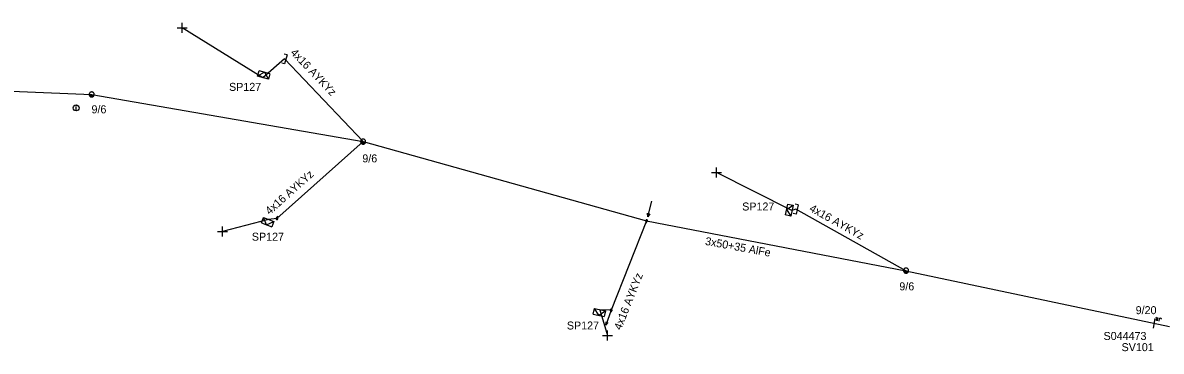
# Model space of a CAD drawing. Extents: x -717562 to -713845, y -1151196 to -1143903.
# Drawn here: x -715067 to -714924.8, y -1150294.6 to -1150253.5 of the extents above; entities that cross this region are included whole.
import ezdxf

# ---------------------------------------------------------------- set-up
doc = ezdxf.new("R2010")
doc.units = 0
for name, color, linetype in [('Vrstva 1', 7, 'Continuous'), ('Vrstva 10', 7, 'Continuous'), ('Vrstva 12', 7, 'Continuous'), ('Vrstva 13', 7, 'Continuous'), ('Vrstva 15', 7, 'Continuous'), ('Vrstva 18', 7, 'Continuous'), ('Vrstva 2', 7, 'Continuous'), ('Vrstva 29', 7, 'Continuous'), ('Vrstva 30', 7, 'Continuous'), ('Vrstva 31', 7, 'Continuous'), ('Vrstva 33', 7, 'Continuous'), ('Vrstva 34', 7, 'Continuous'), ('Vrstva 36', 7, 'Continuous'), ('Vrstva 54', 7, 'Continuous'), ('Vrstva 55', 7, 'Continuous'), ('Vrstva 59', 7, 'Continuous'), ('Vrstva 9', 7, 'Continuous')]:
    doc.layers.add(name, color=color, linetype=linetype)

# ---------------------------------------------------------------- blocks, each defined once
blk = doc.blocks.new('NN440')
at = {"layer": 'Vrstva 2'}
for points in [[(0.63, 0), (0.63, 0.06), (0.62, 0.13), (0.6, 0.19), (0.58, 0.25), (0.55, 0.31), (0.51, 0.37), (0.47, 0.42), (0.42, 0.46), (0.37, 0.51), (0.32, 0.54), (0.26, 0.57), (0.2, 0.59), (0.13, 0.61), (0.07, 0.62), (0, 0.63), (-0.06, 0.62), (-0.13, 0.61), (-0.19, 0.59), (-0.26, 0.57), (-0.31, 0.54), (-0.37, 0.51), (-0.42, 0.46), (-0.47, 0.42), (-0.51, 0.37), (-0.54, 0.31), (-0.57, 0.25), (-0.6, 0.19), (-0.62, 0.13), (-0.63, 0.06), (-0.63, 0), (-0.63, -0.07), (-0.62, -0.14), (-0.6, -0.2), (-0.57, -0.26), (-0.54, -0.32), (-0.51, -0.37), (-0.47, -0.43), (-0.42, -0.47), (-0.37, -0.51), (-0.31, -0.55), (-0.26, -0.58), (-0.19, -0.6), (-0.13, -0.62), (-0.06, -0.63), (0, -0.63), (0.07, -0.63), (0.13, -0.62), (0.2, -0.6), (0.26, -0.58), (0.32, -0.55), (0.37, -0.51), (0.42, -0.47), (0.47, -0.43), (0.51, -0.37), (0.55, -0.32), (0.58, -0.26), (0.6, -0.2), (0.62, -0.14), (0.63, -0.07), (0.63, 0)], [(-0.63, 0), (0.63, 0)], [(-0.6, -0.18), (0.57, -0.18)], [(-0.51, -0.32), (0.5, -0.32)], [(-0.37, -0.47), (0.35, -0.47)]]:
    blk.add_lwpolyline(points, dxfattribs=at)
blk = doc.blocks.new('NN560')
at = {"layer": 'Vrstva 2'}
for points in [[(2, 0), (1.59, 0.14)], [(0, 0), (2, 0)], [(2, 0), (1.59, -0.13)]]:
    blk.add_lwpolyline(points, dxfattribs=at)
blk = doc.blocks.new('NN840')
at = {"layer": 'Vrstva 15'}
for points in [[(0, 0.62), (0, -0.63)], [(-0.75, -0.71), (-0.75, -0.66)], [(-0.73, -0.76), (-0.75, -0.71)], [(-0.66, -0.8), (-0.73, -0.76)], [(-0.63, -0.8), (-0.66, -0.8)], [(-0.56, -0.76), (-0.63, -0.8)], [(-0.54, -0.71), (-0.56, -0.76)], [(-0.54, -0.38), (-0.54, -0.71)], [(-0.33, -0.38), (-0.33, -0.8)], [(-0.33, -0.64), (-0.13, -0.38)], [(-0.26, -0.56), (-0.09, -0.8)]]:
    blk.add_lwpolyline(points, dxfattribs=at)
blk = doc.blocks.new('NN565')
at = {"layer": 'Vrstva 2'}
for points in [[(0.01, 0.53), (0.01, 2.53)], [(0.16, 0.94), (0.01, 0.53), (-0.12, 0.94)]]:
    blk.add_lwpolyline(points, dxfattribs=at)
blk = doc.blocks.new('NN770')
at = {"layer": 'Vrstva 10'}
for p, q in [((0, 0.19), (0, 0.26)), ((0, -0.28), (0, 0.11))]:
    blk.add_line(p, q, dxfattribs=at)
blk.add_circle((0, -0.01), 0.375, dxfattribs=at)
blk = doc.blocks.new('NN800')
at = {"layer": 'Vrstva 1'}
for points in [[(-0.44, 0.44), (0.44, -0.44)], [(-0.44, -0.44), (0.44, 0.44)]]:
    blk.add_lwpolyline(points, dxfattribs=at)
blk = doc.blocks.new('NN630')
at = {"layer": 'Vrstva 9'}
for points in [[(0, -0.7), (-0.7, 0)], [(-0.7, -0.7), (-0.7, 0), (0.7, 0), (0.7, -0.7)], [(-0.7, -0.7), (0.7, -0.7)], [(0, -0.7), (0.7, 0)]]:
    blk.add_lwpolyline(points, dxfattribs=at)
blk = doc.blocks.new('NN500')
at = {"layer": 'Vrstva 2'}
for points in [[(0, -0.24), (0.02, -0.23), (0.05, -0.23), (0.07, -0.22), (0.09, -0.22), (0.12, -0.2), (0.14, -0.19), (0.16, -0.18), (0.17, -0.16), (0.19, -0.14), (0.2, -0.12), (0.21, -0.1), (0.22, -0.07), (0.23, -0.05), (0.23, -0.02), (0.23, 0), (0.23, 0.02), (0.23, 0.05), (0.22, 0.07), (0.21, 0.1), (0.2, 0.12), (0.19, 0.14), (0.17, 0.16), (0.16, 0.17), (0.14, 0.19), (0.12, 0.2), (0.09, 0.21), (0.07, 0.22), (0.05, 0.23), (0.02, 0.23), (0, 0.23), (-0.03, 0.23), (-0.05, 0.23), (-0.07, 0.22), (-0.1, 0.21), (-0.12, 0.2), (-0.14, 0.19), (-0.16, 0.17), (-0.18, 0.16), (-0.19, 0.14), (-0.2, 0.12), (-0.22, 0.1), (-0.22, 0.07), (-0.23, 0.05), (-0.23, 0.02), (-0.24, 0), (-0.23, -0.02), (-0.23, -0.05), (-0.22, -0.07), (-0.22, -0.1), (-0.2, -0.12), (-0.19, -0.14), (-0.18, -0.16), (-0.16, -0.18), (-0.14, -0.19), (-0.12, -0.2), (-0.1, -0.22), (-0.07, -0.22), (-0.05, -0.23), (-0.03, -0.23), (0, -0.24)], [(0, -0.24), (0.02, -0.23), (0.05, -0.23), (0.07, -0.22), (0.09, -0.22), (0.12, -0.2), (0.14, -0.19), (0.16, -0.18), (0.17, -0.16), (0.19, -0.14), (0.2, -0.12), (0.21, -0.1), (0.22, -0.07), (0.23, -0.05), (0.23, -0.02), (0.23, 0), (0.23, 0.02), (0.23, 0.05), (0.22, 0.07), (0.21, 0.1), (0.2, 0.12), (0.19, 0.14), (0.17, 0.16), (0.16, 0.17), (0.14, 0.19), (0.12, 0.2), (0.09, 0.21), (0.07, 0.22), (0.05, 0.23), (0.02, 0.23), (0, 0.23), (-0.03, 0.23), (-0.05, 0.23), (-0.07, 0.22), (-0.1, 0.21), (-0.12, 0.2), (-0.14, 0.19), (-0.16, 0.17), (-0.18, 0.16), (-0.19, 0.14), (-0.2, 0.12), (-0.22, 0.1), (-0.22, 0.07), (-0.23, 0.05), (-0.23, 0.02), (-0.24, 0), (-0.23, -0.02), (-0.23, -0.05), (-0.22, -0.07), (-0.22, -0.1), (-0.2, -0.12), (-0.19, -0.14), (-0.18, -0.16), (-0.16, -0.18), (-0.14, -0.19), (-0.12, -0.2), (-0.1, -0.22), (-0.07, -0.22), (-0.05, -0.23), (-0.03, -0.23), (0, -0.24)], [(0, -0.21), (0.02, -0.2), (0.04, -0.2), (0.06, -0.2), (0.08, -0.19), (0.1, -0.18), (0.12, -0.17), (0.14, -0.15), (0.15, -0.14), (0.16, -0.12), (0.18, -0.1), (0.19, -0.08), (0.19, -0.06), (0.2, -0.04), (0.2, -0.02), (0.2, 0), (0.2, 0.02), (0.2, 0.04), (0.19, 0.06), (0.19, 0.08), (0.18, 0.1), (0.16, 0.12), (0.15, 0.14), (0.14, 0.15), (0.12, 0.17), (0.1, 0.18), (0.08, 0.19), (0.06, 0.19), (0.04, 0.2), (0.02, 0.2), (0, 0.2), (-0.02, 0.2), (-0.04, 0.2), (-0.06, 0.19), (-0.08, 0.19), (-0.1, 0.18), (-0.12, 0.17), (-0.14, 0.15), (-0.15, 0.14), (-0.17, 0.12), (-0.18, 0.1), (-0.19, 0.08), (-0.2, 0.06), (-0.2, 0.04), (-0.21, 0.02), (-0.21, 0), (-0.21, -0.02), (-0.2, -0.04), (-0.2, -0.06), (-0.19, -0.08), (-0.18, -0.1), (-0.17, -0.12), (-0.15, -0.14), (-0.14, -0.15), (-0.12, -0.17), (-0.1, -0.18), (-0.08, -0.19), (-0.06, -0.2), (-0.04, -0.2), (-0.02, -0.2), (0, -0.21)], [(0, -0.18), (0.02, -0.18), (0.04, -0.17), (0.05, -0.17), (0.07, -0.16), (0.09, -0.15), (0.1, -0.14), (0.12, -0.13), (0.13, -0.12), (0.14, -0.1), (0.15, -0.09), (0.16, -0.07), (0.17, -0.05), (0.17, -0.04), (0.17, -0.02), (0.17, 0), (0.17, 0.02), (0.17, 0.04), (0.17, 0.05), (0.16, 0.07), (0.15, 0.09), (0.14, 0.1), (0.13, 0.12), (0.12, 0.13), (0.1, 0.14), (0.09, 0.15), (0.07, 0.16), (0.05, 0.17), (0.04, 0.17), (0.02, 0.17), (0, 0.18), (-0.02, 0.17), (-0.04, 0.17), (-0.06, 0.17), (-0.07, 0.16), (-0.09, 0.15), (-0.1, 0.14), (-0.12, 0.13), (-0.13, 0.12), (-0.14, 0.1), (-0.15, 0.09), (-0.16, 0.07), (-0.17, 0.05), (-0.17, 0.04), (-0.18, 0.02), (-0.18, 0), (-0.18, -0.02), (-0.17, -0.04), (-0.17, -0.05), (-0.16, -0.07), (-0.15, -0.09), (-0.14, -0.1), (-0.13, -0.12), (-0.12, -0.13), (-0.1, -0.14), (-0.09, -0.15), (-0.07, -0.16), (-0.06, -0.17), (-0.04, -0.17), (-0.02, -0.18), (0, -0.18)], [(0, -0.15), (0.01, -0.15), (0.03, -0.14), (0.04, -0.14), (0.06, -0.13), (0.07, -0.13), (0.08, -0.12), (0.1, -0.11), (0.11, -0.1), (0.12, -0.09), (0.13, -0.07), (0.13, -0.06), (0.14, -0.05), (0.14, -0.03), (0.14, -0.02), (0.14, 0), (0.14, 0.01), (0.14, 0.03), (0.14, 0.04), (0.13, 0.06), (0.13, 0.07), (0.12, 0.09), (0.11, 0.1), (0.1, 0.11), (0.08, 0.12), (0.07, 0.13), (0.06, 0.13), (0.04, 0.14), (0.03, 0.14), (0.01, 0.14), (0, 0.15), (-0.02, 0.14), (-0.03, 0.14), (-0.05, 0.14), (-0.06, 0.13), (-0.07, 0.13), (-0.09, 0.12), (-0.1, 0.11), (-0.11, 0.1), (-0.12, 0.09), (-0.13, 0.07), (-0.13, 0.06), (-0.14, 0.04), (-0.14, 0.03), (-0.15, 0.01), (-0.15, 0), (-0.15, -0.02), (-0.14, -0.03), (-0.14, -0.05), (-0.13, -0.06), (-0.13, -0.07), (-0.12, -0.09), (-0.11, -0.1), (-0.1, -0.11), (-0.09, -0.12), (-0.07, -0.13), (-0.06, -0.13), (-0.05, -0.14), (-0.03, -0.14), (-0.02, -0.15), (0, -0.15)], [(0, -0.12), (0.01, -0.12), (0.02, -0.11), (0.03, -0.11), (0.05, -0.11), (0.06, -0.1), (0.07, -0.09), (0.08, -0.09), (0.09, -0.08), (0.09, -0.07), (0.1, -0.06), (0.11, -0.05), (0.11, -0.04), (0.11, -0.02), (0.11, -0.01), (0.12, 0), (0.11, 0.01), (0.11, 0.02), (0.11, 0.04), (0.11, 0.05), (0.1, 0.06), (0.09, 0.07), (0.09, 0.08), (0.08, 0.09), (0.07, 0.09), (0.06, 0.1), (0.05, 0.11), (0.03, 0.11), (0.02, 0.11), (0.01, 0.12), (0, 0.12), (-0.01, 0.12), (-0.03, 0.11), (-0.04, 0.11), (-0.05, 0.11), (-0.06, 0.1), (-0.07, 0.09), (-0.08, 0.09), (-0.09, 0.08), (-0.1, 0.07), (-0.1, 0.06), (-0.11, 0.05), (-0.11, 0.04), (-0.12, 0.02), (-0.12, 0.01), (-0.12, 0), (-0.12, -0.01), (-0.12, -0.02), (-0.11, -0.04), (-0.11, -0.05), (-0.1, -0.06), (-0.1, -0.07), (-0.09, -0.08), (-0.08, -0.09), (-0.07, -0.09), (-0.06, -0.1), (-0.05, -0.11), (-0.04, -0.11), (-0.03, -0.11), (-0.01, -0.12), (0, -0.12)], [(0, -0.09), (0.01, -0.09), (0.02, -0.09), (0.03, -0.08), (0.03, -0.08), (0.04, -0.08), (0.05, -0.07), (0.06, -0.07), (0.06, -0.06), (0.07, -0.05), (0.07, -0.04), (0.08, -0.04), (0.08, -0.03), (0.08, -0.02), (0.09, -0.01), (0.09, 0), (0.09, 0.01), (0.08, 0.02), (0.08, 0.03), (0.08, 0.03), (0.07, 0.04), (0.07, 0.05), (0.06, 0.06), (0.06, 0.06), (0.05, 0.07), (0.04, 0.07), (0.03, 0.08), (0.03, 0.08), (0.02, 0.08), (0.01, 0.09), (0, 0.09), (-0.01, 0.09), (-0.02, 0.08), (-0.03, 0.08), (-0.04, 0.08), (-0.04, 0.07), (-0.05, 0.07), (-0.06, 0.06), (-0.07, 0.06), (-0.07, 0.05), (-0.08, 0.04), (-0.08, 0.03), (-0.08, 0.03), (-0.09, 0.02), (-0.09, 0.01), (-0.09, 0), (-0.09, -0.01), (-0.09, -0.02), (-0.08, -0.03), (-0.08, -0.04), (-0.08, -0.04), (-0.07, -0.05), (-0.07, -0.06), (-0.06, -0.07), (-0.05, -0.07), (-0.04, -0.08), (-0.04, -0.08), (-0.03, -0.08), (-0.02, -0.09), (-0.01, -0.09), (0, -0.09)], [(0, -0.06), (0, -0.06), (0.01, -0.06), (0.02, -0.05), (0.02, -0.05), (0.03, -0.05), (0.03, -0.05), (0.04, -0.04), (0.04, -0.04), (0.05, -0.03), (0.05, -0.03), (0.05, -0.02), (0.05, -0.02), (0.05, -0.01), (0.06, -0.01), (0.06, 0), (0.06, 0.01), (0.05, 0.01), (0.05, 0.02), (0.05, 0.02), (0.05, 0.03), (0.05, 0.03), (0.04, 0.04), (0.04, 0.04), (0.03, 0.05), (0.03, 0.05), (0.02, 0.05), (0.02, 0.05), (0.01, 0.06), (0, 0.06), (0, 0.06), (-0.01, 0.06), (-0.01, 0.06), (-0.02, 0.05), (-0.02, 0.05), (-0.03, 0.05), (-0.03, 0.05), (-0.04, 0.04), (-0.04, 0.04), (-0.05, 0.03), (-0.05, 0.03), (-0.05, 0.02), (-0.06, 0.02), (-0.06, 0.01), (-0.06, 0.01), (-0.06, 0), (-0.06, -0.01), (-0.06, -0.01), (-0.06, -0.02), (-0.05, -0.02), (-0.05, -0.03), (-0.05, -0.03), (-0.04, -0.04), (-0.04, -0.04), (-0.03, -0.05), (-0.03, -0.05), (-0.02, -0.05), (-0.02, -0.05), (-0.01, -0.06), (-0.01, -0.06), (0, -0.06)], [(0, -0.03), (0, -0.03), (0, -0.03), (0.01, -0.03), (0.01, -0.03), (0.01, -0.02), (0.02, -0.02), (0.02, -0.02), (0.02, -0.02), (0.02, -0.02), (0.02, -0.01), (0.02, -0.01), (0.03, -0.01), (0.03, -0.01), (0.03, 0), (0.03, 0), (0.03, 0), (0.03, 0.01), (0.03, 0.01), (0.02, 0.01), (0.02, 0.01), (0.02, 0.02), (0.02, 0.02), (0.02, 0.02), (0.02, 0.02), (0.01, 0.02), (0.01, 0.02), (0.01, 0.03), (0, 0.03), (0, 0.03), (0, 0.03), (0, 0.03), (-0.01, 0.03), (-0.01, 0.03), (-0.01, 0.02), (-0.02, 0.02), (-0.02, 0.02), (-0.02, 0.02), (-0.02, 0.02), (-0.02, 0.02), (-0.03, 0.01), (-0.03, 0.01), (-0.03, 0.01), (-0.03, 0.01), (-0.03, 0), (-0.03, 0), (-0.03, 0), (-0.03, -0.01), (-0.03, -0.01), (-0.03, -0.01), (-0.03, -0.01), (-0.02, -0.02), (-0.02, -0.02), (-0.02, -0.02), (-0.02, -0.02), (-0.02, -0.02), (-0.01, -0.03), (-0.01, -0.03), (-0.01, -0.03), (0, -0.03), (0, -0.03)], [(0.23, 0), (0.7, 0)]]:
    blk.add_lwpolyline(points, dxfattribs=at)
blk = doc.blocks.new('NN515')
at = {"layer": 'Vrstva 2'}
for points in [[(-0.59, 0.18), (0.59, 0.18)], [(-0.59, 0.18), (-0.59, -0.18)], [(0.59, 0.18), (0.59, -0.18)]]:
    blk.add_lwpolyline(points, dxfattribs=at)

msp = doc.modelspace()

# ---------------------------------------------------------------- linework, layer by layer
at = {"layer": 'Vrstva 1'}
msp.add_lwpolyline([(-715091.6, -1150261.12), (-715058.41, -1150262.48), (-715024.51, -1150268.38), (-714989.1, -1150278.29), (-714956.7, -1150284.53), (-714923.79, -1150291.53)], dxfattribs=at)
at = {"layer": 'Vrstva 54'}
for points in [[(-715024.51, -1150268.38), (-715034.34, -1150258.04), (-715037.02, -1150260.38)], [(-715024.51, -1150268.38), (-715035.28, -1150278.01), (-715036.32, -1150278.14)], [(-714956.7, -1150284.53), (-714970.48, -1150276.83), (-714970.95, -1150277.02)], [(-714989.1, -1150278.29), (-714993.53, -1150289.48), (-714994.94, -1150289.42)]]:
    msp.add_lwpolyline(points, dxfattribs=at)
at = {"layer": 'Vrstva 59'}
for points in [[(-715037.02, -1150260.38), (-715047.13, -1150254.13)], [(-714970.95, -1150277.02), (-714980.38, -1150272.25)], [(-715036.32, -1150278.14), (-715042.06, -1150279.63)], [(-714994.94, -1150289.42), (-714994, -1150292.63)]]:
    msp.add_lwpolyline(points, dxfattribs=at)

# ---------------------------------------------------------------- block references
at = {"layer": 'Vrstva 13'}
for name, p, rotation in [('NN515', (-715034.34, -1150258.04), -105.27964166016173), ('NN565', (-714989.1, -1150278.29), -14.43597493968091), ('NN515', (-714970.48, -1150276.83), -102.05542501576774), ('NN560', (-714993.53, -1150289.47), -108.8508428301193)]:
    msp.add_blockref(name, p, dxfattribs=dict(at, rotation=rotation))
for name, p, xscale, yscale, rotation in [('NN440', (-715058.41, -1150262.48), 0.5, 0.49999999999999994, -9.868230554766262), ('NN440', (-715024.51, -1150268.38), 0.49999999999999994, 0.5, -15.646147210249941), ('NN500', (-715035.28, -1150278.01), 0.5000000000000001, 0.5, 69.17399996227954), ('NN500', (-714989.1, -1150278.29), 0.5, 0.5, -105.64599998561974), ('NN440', (-714956.69, -1150284.52), 0.49999999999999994, 0.5000000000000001, -10.409872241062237), ('NN500', (-714993.53, -1150289.48), 0.5, 0.5, -101.9079999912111)]:
    msp.add_blockref(name, p, dxfattribs=dict(at, xscale=xscale, yscale=yscale, rotation=rotation))
at = {"layer": 'Vrstva 18', "rotation": 169.59012775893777}
msp.add_blockref('NN840', (-714925.69, -1150291.12), dxfattribs=at)
at = {"layer": 'Vrstva 31'}
for p, rotation in [((-715037.02, -1150260.38), 164.81239444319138), ((-714970.95, -1150277.02), -102.05542501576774), ((-715036.32, -1150278.14), -20.826130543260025), ((-714994.94, -1150289.42), -11.907686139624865)]:
    msp.add_blockref('NN630', p, dxfattribs=dict(at, rotation=rotation))
at = {"layer": 'Vrstva 34', "rotation": 45}
for p in [(-715047.13, -1150254.13), (-714980.38, -1150272.25), (-715042.06, -1150279.63), (-714994, -1150292.63)]:
    msp.add_blockref('NN800', p, dxfattribs=at)
at = {"layer": 'Vrstva 36'}
msp.add_blockref('NN770', (-715060.36, -1150264.15), dxfattribs=at)

# ---------------------------------------------------------------- texts
at = {"layer": 'Vrstva 12'}
for s, p in [('9/6', (-715058.44, -1150264.84)), ('9/6', (-715024.61, -1150270.98)), ('9/6', (-714957.53, -1150286.99)), ('9/20', (-714928.01, -1150289.97))]:
    msp.add_text(s, height=1, dxfattribs=at).set_placement(p)
at = {"layer": 'Vrstva 2'}
msp.add_text('3x50+35 AlFe', height=1, rotation=349.59, dxfattribs=at).set_placement((-714981.85, -1150281.29))
at = {"layer": 'Vrstva 29'}
msp.add_text('S044473', height=1, dxfattribs=at).set_placement((-714932.02, -1150293.2))
at = {"layer": 'Vrstva 30'}
msp.add_text('SV101', height=1, dxfattribs=at).set_placement((-714929.77, -1150294.6))
at = {"layer": 'Vrstva 33'}
for p in [(-715041.26, -1150262.03), (-714977.16, -1150277), (-715038.41, -1150280.78), (-714999.06, -1150291.89)]:
    msp.add_text('SP127', height=1, dxfattribs=at).set_placement(p)
at = {"layer": 'Vrstva 55'}
for rotation, p in [(313.58, (-715033.65, -1150257.32)), (41.79, (-715036.19, -1150277.6)), (330.822, (-714968.86, -1150277.02)), (68.404, (-714992.3, -1150292.03))]:
    msp.add_text('4x16 AYKYz', height=1, rotation=rotation, dxfattribs=at).set_placement(p)

doc.saveas('drawing.dxf')
